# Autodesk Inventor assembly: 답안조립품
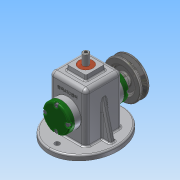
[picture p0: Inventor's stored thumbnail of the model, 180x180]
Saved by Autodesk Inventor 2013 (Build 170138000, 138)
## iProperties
Created: 2017-07
Part Number: 답안조립품
Document SubType Name: Assembly
Designer: Administrator
Author: Administrator
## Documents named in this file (16)
- C:\Users\Administrator\Desktop\470707V1019\답안조립품.iam
- C:\Users\Administrator\Desktop\470707V1019\본체.ipt
- C:\Users\Administrator\Desktop\470707V1019\앞커버.ipt
- C:\Users\Administrator\Desktop\470707V1019\뒤커버.ipt
- C:\Users\Administrator\Desktop\470707V1019\베어링 12 x 32 x 10.ipt
- C:\Users\Administrator\Desktop\470707V1019\편심축.ipt
- C:\Users\Administrator\Desktop\470707V1019\링크.ipt
- C:\Users\Administrator\Desktop\470707V1019\슬라이드.ipt
- C:\Users\Administrator\Desktop\470707V1019\오일실 12 25 7.ipt
- C:\Users\Administrator\Desktop\470707V1019\V벨트풀리.ipt
- C:\Users\Administrator\Desktop\470707V1019\고정핀 1.2 x  8.ipt
- C:\Users\Administrator\Desktop\470707V1019\멈춤나사 M3x8.ipt
- C:\Users\Administrator\Desktop\470707V1019\볼트 M4 x 12.ipt
- C:\Users\Administrator\Desktop\470707V1019\부시.ipt
- C:\Users\Administrator\Desktop\470707V1019\키 4 x 4 x 10.ipt
- C:\Users\Administrator\Desktop\470707V1019\핀 5 x 18.ipt
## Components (3 placed, 3 different names)
1. V벨트풀리:1 — 각도:3, 플러쉬:4
2. 고정핀 1.2 x  8:1
3. 핀 5 x 18:1
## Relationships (2: Angle 1, Flush 1)
- 각도:3 [Angle]: V벨트풀리:1
- 플러쉬:4 [Flush]: V벨트풀리:1
